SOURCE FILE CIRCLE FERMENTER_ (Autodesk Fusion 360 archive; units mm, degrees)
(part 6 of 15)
sketch "Schizzo15" plane through (40, 0, 0) normal (-1, 0, 0) x axis (0, -1, 0)
  line L1 (88.4, -53.5) -> (90, -53.5)
  line L2 (88.4, -63.5) -> (88.4, -53.5)
  line L3 (85.4, -63.5) -> (88.4, -63.5)
  curve K1 (78.4501, -76.9501) -> (85.4, -63.5)
  curve K2 (65, -83.9) -> (78.4501, -76.9501)
  line L4 (65, -86.9) -> (65, -83.9)
  line L5 (55, -86.9) -> (65, -86.9)
  line L6 (55, -88.5) -> (55, -86.9)
  line L7 (65, -88.5) -> (55, -88.5)
  curve K3 (90, -63.5) -> (65, -88.5)
  line L8 (90, -53.5) -> (90, -63.5)
  line L9 (94.1435, -92.6435) -> (78.4501, -76.9501)
  line L10 (61.8584, -76.9501) -> (78.4501, -76.9501)
  line L11 (86.9521, -65.1) -> (88.4, -65.1)
  curve K4 (79.1128, -78.5501) -> (86.9521, -65.1)
  line L12 (61.8584, -78.5501) -> (79.1128, -78.5501)
  curve K5 (88.4, -63.5) -> (65, -86.9)
  curve K6 (66.6, -85.4521) -> (79.5815, -78.0815)
  line L13 (66.6, -86.9) -> (66.6, -85.4521)
  point P6 (78.4501, -76.9501)
  point P13 (78.4501, -76.9501)
  coincident P6 P13
  horizontal L10
  dimension "d265_1" angle L9 L10 = 135
  dimension "d266_1" = -1.6
  dimension "d267_1" = -1.6
  dimension "d268_1" = -1.6
extrude "Estrusione18" cut sketch "Schizzo15" profile of L11 K4 K5 K6 L13 against normal blind 70 named "d269_1"
sketch "Schizzo16" plane through (0, -15, 0) normal (0, 1, 0) x axis (-1, 0, 0)
  line L1 (-125, -86.9) -> (-125, -88.5)
  line L2 (-135, -86.9) -> (-125, -86.9)
  line L3 (-135, -83.9) -> (-135, -86.9)
  curve K1 (-135, -83.9) -> (-142.5, -79.9)
  curve K2 (-142.5, -79.9) -> (-160, -86.9)
  line L4 (-160, -88.5) -> (-160, -86.9)
  line L5 (-125, -88.5) -> (-160, -88.5)
  curve K3 (-135, -85.5) -> (-142.5, -81.5)
  curve K4 (-142.5, -81.5) -> (-152.9954, -86.9)
  line L6 (-125, -86.9) -> (-152.9954, -86.9)
  line L7 (-136.6, -83.9) -> (-136.6, -86.9)
  line L8 (-138.6, -84.5053) -> (-138.6, -86.9)
  point P15 (-138.6, -86.9)
  point P16 (-138.6, -84.5053)
  coincident L6 P15
  coincident K3 P16
  perpendicular L6 L8
  dimension "d271_1" = -1.6
  dimension "d272_1" = -1.6
  dimension "d673_1" distance L7 L8 = 2
extrude "Estrusione19" cut sketch "Schizzo16" profile of K3 K4 L6 L8 against normal blind 50 named "d273_1"
sketch "Schizzo17" plane through (0, 0, -13.5) normal (0, 0, 1) x axis (-1, 0, 0)
  line L1 (-125, 90) -> (-125, 88.4)
  line L2 (-160, 90) -> (-125, 90)
  line L3 (-160, 88.4) -> (-160, 90)
  curve K1 (-142.5, 81.4) -> (-160, 88.4)
  curve K2 (-135, 85.4) -> (-142.5, 81.4)
  line L4 (-135, 88.4) -> (-135, 85.4)
  line L5 (-125, 88.4) -> (-135, 88.4)
  line L6 (-136.6, 88.4) -> (-136.6, 86.8515)
  line L7 (-152.9954, 88.4) -> (-136.6, 88.4)
  curve K3 (-142.5, 83) -> (-152.9954, 88.4)
  curve K4 (-136.6, 86.8515) -> (-142.5, 83)
  line L8 (-138.6, 88.4) -> (-138.6, 86.0053)
  point P13 (-138.6, 86.0053)
  point P14 (-138.6, 88.4)
  coincident K4 P13
  coincident L7 P14
  perpendicular L7 L8
  dimension "d275_1" = -1.6
  dimension "d672_1" distance L6 L8 = 2
extrude "Estrusione20" cut sketch "Schizzo17" profile of K3 K4 L7 L8 against normal blind 50 named "d276_1"
sweep "Sweep3" TwistAngle 0 named "d289_1" TaperAngle 0 named "d290_1"
fillet "Raccordo1" radius 0.5 named "d292_1"
extrude "Estrusione21" cut of existing geometry blind -45 (= "-120 mm + 75 mm") named "d293_1"
sketch "Schizzo18" plane through (0, -15, 0) normal (0, 1, 0) x axis (-1, 0, 0)
  line L1 (-150.8209, -86.9) -> (-138.6, -86.9)
  curve K1 (-150.8209, -86.9) -> (-151.0572, -85.9594)
  curve K2 (-142.5, -81.5) -> (-151.0572, -85.9594)
  curve K3 (-138.6, -84.5053) -> (-142.5, -81.5)
  line L2 (-125, -86.9) -> (-125, -88.5)
  line L3 (-135, -86.9) -> (-125, -86.9)
  line L4 (-135, -83.9) -> (-135, -86.9)
  curve K4 (-135, -83.9) -> (-142.5, -79.9)
  curve K5 (-142.5, -79.9) -> (-160, -86.9)
  line L5 (-160, -88.5) -> (-160, -86.9)
  line L6 (-125, -88.5) -> (-160, -88.5)
  line L7 (-138.6, -86.9) -> (-138.6, -84.5053)
  circle C1 centre (-135.4, -85.4) radius 0.85
  point P14 (-135.4, -85.4)
  dimension "DIAM_SEDE_GUARNIZOIONE_1" diameter C1 = 1.7
  dimension "d669_1" distance L4 P14 = 0.4
  dimension "d671_1" distance L3 P14 = 1.5
sweep "Sweep4" sketch "Schizzo18" TwistAngle 0 named "d301_1" TaperAngle 0 named "d302_1"
mirror "Specchio2" mirrorStitchTolerance 0.1 named "d304_1"
sketch "Schizzo19" plane through (0, -15, 0) normal (0, 1, 0) x axis (-1, 0, 0)
  line L1 (-135, -83.9) -> (-135, -84.65)
  curve K1 (-135, -83.9) -> (-142.5, -79.9)
  curve K2 (-142.5, -79.9) -> (-160, -86.9)
  line L2 (-160, -88.5) -> (-160, -86.9)
  line L3 (-125, -88.5) -> (-160, -88.5)
  line L4 (-125, -86.9) -> (-125, -88.5)
  line L5 (-135, -86.9) -> (-125, -86.9)
  line L6 (-150.8209, -86.9) -> (-138.6, -86.9)
  curve K3 (-150.8209, -86.9) -> (-151.0572, -85.9594)
  curve K4 (-142.5, -81.5) -> (-151.0572, -85.9594)
  curve K5 (-138.6, -84.5053) -> (-142.5, -81.5)
  line L7 (-135, -86.15) -> (-135, -86.9)
  line L8 (-138.6, -86.9) -> (-138.6, -84.5053)
  arc A1 centre (-135.4, -85.4) radius 0.85 clockwise from (-135, -86.15) to (-135, -84.65)
  arc A2 centre (-135.4, -85.4) radius 0.85 clockwise from (-135, -86.15) to (-135, -84.65)
  circle C1 centre (-135.4, -85.4) radius 0.875
  concentric A2 C1
  dimension "d305_1" diameter C1 = 1.75
sweep "Sweep5" sketch "Schizzo19" TwistAngle 0 named "d310_1" TaperAngle 0 named "d311_1" bodies "GUARNIZIONE"
mirror "Specchio3" mirrorStitchTolerance 0.1 named "d313_1" bodies "GUARNIZIONE (1)"
work_plane "Piano di lavoro2" AlongDistance -2 named "d328_1"
sketch "Schizzo21" plane through (158, 0, 0) normal (1, 0, 0) x axis (0, 1, 0)
  line L1 (-81.4, -63.5) -> (-81.4, -13.5)
  curve K1 (-81.4, -63.5) -> (-65, -79.9)
  line L2 (-65, -79.9) -> (-15, -79.9)
  line L3 (-65, -81.4) -> (-15, -81.4)
  curve K2 (-82.9, -63.5) -> (-65, -81.4)
  line L4 (-82.9, -63.5) -> (-82.9, -13.5)
  line L5 (-15, -13.5) -> (-15, -81.4)
  line L6 (-82.9, -13.5) -> (-15, -13.5)
  horizontal L6
  vertical L5
  dimension "d329_1" = -1.5
extrude "Estrusione23" new body sketch "Schizzo21" profile of L3 K2 L4 L5 L6 against normal blind 3 named "d330_1" bodies "TEST ACRILICO DAVANTI"
sketch "Schizzo22" plane through (0, 0, -13.5) normal (0, 0, 1) x axis (-1, 0, 0)
  line L1 (-125, 88.4) -> (-135, 88.4)
  line L2 (-125, 90) -> (-125, 88.4)
  line L3 (-160, 90) -> (-125, 90)
  line L4 (-160, 88.4) -> (-160, 90)
  curve K1 (-142.5, 81.4) -> (-160, 88.4)
  curve K2 (-135, 85.4) -> (-142.5, 81.4)
  line L5 (-135, 88.4) -> (-135, 87.65)
  curve K3 (-142.5, 83) -> (-138.6, 86.0053)
  curve K4 (-151.0572, 87.4594) -> (-142.5, 83)
  curve K5 (-151.0572, 87.4594) -> (-150.8209, 88.4)
  line L6 (-138.6, 88.4) -> (-150.8209, 88.4)
  curve K6 (-142.5, 80.9) -> (-160, 87.9)
  line L7 (-160, 90) -> (-160, 87.9)
  line L8 (-158, 15) -> (-158, 82.9)
  line L9 (-155, 15) -> (-158, 15)
  line L10 (-155, 82.9) -> (-155, 15)
  line L11 (-158, 82.9) -> (-155, 82.9)
  line L12 (-158, 82.9) -> (-158, 77.9)
  line L13 (-155, 82.9) -> (-158, 82.9)
  line L14 (-155, 86.9365) -> (-155, 82.9)
  curve K7 (-164, 77.9) -> (-158, 77.9)
  curve K8 (-168, 77.9) -> (-164, 77.9)
  curve K9 (-170, 88.4) -> (-168, 77.9)
  curve K10 (-174, 88.4) -> (-170, 88.4)
  curve K11 (-180, 88.4) -> (-174, 88.4)
  curve K12 (-180, 88.4) -> (-158, 77.9)
  line L15 (-160, 90) -> (-160, 87.9)
  line L16 (-180, 90) -> (-160, 90)
  line L17 (-180, 88.4) -> (-180, 90)
  line L18 (-151.4, 82.9) -> (-155, 82.9)
  line L19 (-151.4, 85.247) -> (-151.4, 82.9)
  line L20 (-138.6, 86.0053) -> (-138.6, 88.4)
  line L21 (-135, 86.15) -> (-135, 85.4)
  arc A1 centre (-135.4, 86.9) radius 0.85 clockwise from (-135, 86.15) to (-135, 87.65)
  point P7 (-160, 90)
  point P18 (-160, 90)
  point P23 (-158, 77.9)
  point P19 (-158, 82.9)
  point P24 (-158, 82.9)
  point P22 (-155, 82.9)
  point P25 (-155, 82.9)
  point P26 (-155, 82.9)
  point P27 (-155, 86.9365)
  point P33 (-160, 90)
  point P36 (-151.4, 85.247)
  point P28 (-164, 77.9)
  point P29 (-168, 77.9)
  point P31 (-174, 88.4)
  point P32 (-180, 88.4)
  point P30 (-170, 88.4)
  point P34 (-180, 90)
  point P35 (-151.4, 82.9)
  coincident P7 P18
  perpendicular L3 L7
  coincident L8 P23
  coincident P19 P24
  perpendicular L11 L12
  coincident P22 P25
  coincident P22 P26
  coincident K6 P27
  perpendicular L11 L14
  horizontal K10
  horizontal K7
  perpendicular L15 L16
  parallel L15 L17
  horizontal K8
  horizontal K11
  coincident P18 P33
  perpendicular L14 L18
  coincident K6 P36
  perpendicular L18 L19
  dimension "d332_1" = 0.5
  dimension "d335_1" distance P23 P24 = 5
  dimension "d336_1" distance L3 L13 = 7.1
  dimension "d337_1" distance P23 P28 = 6
  dimension "d338_1" distance P23 P29 = 10
  dimension "d339_1" distance P31 P32 = 6
  dimension "d340_1" distance P30 P32 = 10
  dimension "d342_1" distance P32 P34 = 1.6
  dimension "d343_1" distance P33 P34 = 20
  dimension "d373_1" distance P25 P35 = 3.6
extrude "Estrusione24" new body sketch "Schizzo22" profile of L4 K6 L7 L8 L11 L12 L13 L14 K12 L15 L16 L17 against normal blind 50 named "d344_1"
sweep "Sweep6" TwistAngle 0 named "d350_1" TaperAngle 0 named "d351_1" bodies "PROFILO BASE PORTA"
remove_body "RimuoviCorpo1"
chamfer "Smusso2" distance 0.8 named "d352_1"
component_from_bodies "Corpo->Comp1"
component_from_bodies "Corpo->Comp2"
extrude "Estrusione1" add of existing geometry blind 27.5 (= "( 205 / 2 ) * 1 mm - 75 mm") named "d353_1"
extrude "Estrusione2" add of existing geometry blind 15 (= "90 mm - 75 mm") named "d355_1"
extrude "Estrusione3" add of existing geometry blind 85 (= "( 320 / 2 ) * 1 mm - 75 mm") named "d357_1"
extrude "Estrusione1" add of existing geometry blind 15 named "d359_1"
extrude "Estrusione2" add of existing geometry blind 27.5 named "d361_1"
sketch "Schizzo3" plane through (0, 0, 0) normal (0, 1, 0) x axis (-1, 0, 0)
  line L1 (-160, -87.7) -> (-160.8, -88.5)
  line L2 (-160, -86.4) -> (-160, -87.7)
  curve K1 (-151.4, -83.747) -> (-160, -86.4)
  line L3 (-151.4, -81.4) -> (-151.4, -83.747)
  line L4 (-158, -81.4) -> (-151.4, -81.4)
  line L5 (-158, -76.4) -> (-158, -81.4)
  curve K2 (-180, -86.9) -> (-158, -76.4)
  line L6 (-180, -88.5) -> (-180, -86.9)
  line L7 (-160.8, -88.5) -> (-180, -88.5)
  line L8 (-158, -86.2311) -> (-158, -81.4)
  point P7 (-158, -81.4)
  point P11 (-158, -81.4)
  point P12 (-158, -86.2311)
  coincident P7 P11
  coincident K1 P12
  perpendicular L4 L8
extrude "Estrusione5" cut sketch "Schizzo3" profile of K1 L3 L4 L8 against normal blind 65 named "d384_1"
sketch "Schizzo4" plane through (0, 0, 14) normal (0, 0, 1) x axis (-1, 0, 0)
  line L1 (-160.8, 90) -> (-160, 89.2)
  line L2 (-180, 90) -> (-160.8, 90)
  line L3 (-180, 88.4) -> (-180, 90)
  curve K1 (-158, 77.9) -> (-180, 88.4)
  line L4 (-158, 82.9) -> (-158, 77.9)
  line L5 (-151.4, 82.9) -> (-158, 82.9)
  line L6 (-151.4, 85.247) -> (-151.4, 82.9)
  curve K2 (-160, 87.9) -> (-151.4, 85.247)
  line L7 (-160, 89.2) -> (-160, 87.9)
  line L8 (-158, 87.7311) -> (-158, 82.9)
  point P7 (-158, 82.9)
  point P11 (-158, 82.9)
  point P12 (-158, 87.7311)
  coincident P7 P11
  coincident K2 P12
  perpendicular L5 L8
extrude "Estrusione6" cut sketch "Schizzo4" profile of L5 L6 K2 L8 against normal blind 77.5 named "d386_1"
sketch "Schizzo6" plane through (158, 0, 0) normal (-1, 0, 0) x axis (0, -1, 0)
  curve K1 (65, -76.4) -> (77.9, -63.5)
  line L1 (0, -76.4) -> (65, -76.4)
  line L2 (0, -86.2311) -> (0, -76.4)
  line L3 (0, -86.2311) -> (65, -86.2311)
  line L4 (65, -81.4) -> (65, -86.2311)
  curve K2 (65, -81.4) -> (82.9, -63.5)
  line L5 (87.7311, -63.5) -> (82.9, -63.5)
  line L6 (87.7311, -63.5) -> (87.7311, 14)
  line L7 (77.9, 14) -> (87.7311, 14)
  line L8 (77.9, -63.5) -> (77.9, 14)
  line L9 (86.9, -62.4362) -> (86.9, -63.5)
  line L10 (86.9, 14) -> (86.9, -62.4362)
  line L11 (0, -85.4) -> (65, -85.4)
  line L12 (0, 14) -> (0, -85.4)
  line L13 (86.9, 14) -> (0, 14)
  point P12 (86.9, -63.5)
  point P14 (86.9, 14)
  point P15 (65, -85.4)
  point P16 (0, -85.4)
  coincident L5 P12
  perpendicular L5 L9
  coincident L7 P14
  perpendicular L7 L10
  coincident L4 P15
  coincident L2 P16
  perpendicular L2 L11
  horizontal L13
  vertical L12
  dimension "d398_1" distance L10 L12 = 86.9
  dimension "d399_1" distance L11 L13 = 99.4
extrude "Estrusione7" new body sketch "Schizzo6" profile of K1 L1 L2 L4 K2 L5 L7 L8 L9 L10 L11 L12 L13 along normal blind 3 named "d396_1" bodies "ACRILICO SPORTELLO"
sketch "Schizzo7" plane through (0, 0, 14) normal (0, 0, 1) x axis (-1, 0, 0)
  line L1 (-158, 87.7311) -> (-158, 77.9)
  curve K1 (-160, 87.9) -> (-158, 87.7311)
  line L2 (-160, 89.2) -> (-160, 87.9)
  line L3 (-160.8, 90) -> (-160, 89.2)
  line L4 (-180, 90) -> (-160.8, 90)
  line L5 (-180, 88.4) -> (-180, 90)
  curve K2 (-158, 77.9) -> (-180, 88.4)
  line L6 (-151.4, 85.247) -> (-151.4, 82.9)
  curve K3 (-151.4, 85.247) -> (-158, 87.7311)
  line L7 (-158, 82.9) -> (-158, 87.7311)
  line L8 (-151.4, 82.9) -> (-158, 82.9)
  line L9 (-158, 0) -> (-158, 86.9)
  line L10 (-155, 0) -> (-158, 0)
  line L11 (-155, 86.9) -> (-155, 0)
  line L12 (-158, 86.9) -> (-155, 86.9)
  line L13 (-155, 88.0285) -> (-155, 86.9)
  point P16 (-155, 86.9)
  point P17 (-155, 86.9)
  coincident P16 P17
  perpendicular L12 L13
extrude "Estrusione8" new body sketch "Schizzo7" profile of L6 K3 L8 L11 L13 against normal blind 77.5 named "d400_1"
sketch "Schizzo8" plane through (0, 0, 0) normal (0, 1, 0) x axis (-1, 0, 0)
  line L1 (-158, -76.4) -> (-158, -86.2311)
  curve K1 (-180, -86.9) -> (-158, -76.4)
  line L2 (-180, -88.5) -> (-180, -86.9)
  line L3 (-160.8, -88.5) -> (-180, -88.5)
  line L4 (-160, -87.7) -> (-160.8, -88.5)
  line L5 (-160, -86.4) -> (-160, -87.7)
  curve K2 (-158, -86.2311) -> (-160, -86.4)
  line L6 (-158, -85.4) -> (-158, 14)
  line L7 (-155, -85.4) -> (-158, -85.4)
  line L8 (-155, 14) -> (-155, -85.4)
  line L9 (-158, 14) -> (-155, 14)
  line L10 (-158, -86.2311) -> (-158, -81.4)
  curve K3 (-151.4, -83.747) -> (-158, -86.2311)
  line L11 (-151.4, -81.4) -> (-151.4, -83.747)
  line L12 (-158, -81.4) -> (-151.4, -81.4)
  line L13 (-155, -87.0144) -> (-155, -85.4)
  point P11 (-155, -85.4)
  point P17 (-155, -85.4)
  coincident P11 P17
  perpendicular L7 L13
extrude "Estrusione9" new body sketch "Schizzo8" profile of L8 K3 L11 L12 L13 against normal blind 65 named "d402_1"
sketch "Schizzo9" plane through (155, 0, 0) normal (-1, 0, 0) x axis (0, -1, 0)
  line L1 (65, -81.4) -> (65, -85.4)
  curve K1 (82.9, -63.5) -> (65, -81.4)
  line L2 (86.9, -63.5) -> (82.9, -63.5)
  line L3 (86.9, 14) -> (86.9, -63.5)
  line L4 (0, 14) -> (86.9, 14)
  line L5 (0, -85.4) -> (0, 14)
  line L6 (65, -85.4) -> (0, -85.4)
  curve K2 (65, -76.4) -> (77.9, -63.5)
  line L7 (77.9, 14) -> (77.9, -63.5)
  line L8 (0, -76.4) -> (65, -76.4)
  line L9 (65, -81.4) -> (0, -81.4)
  line L10 (82.9, 14) -> (85.247, 14)
  line L11 (82.9, -63.5) -> (82.9, 14)
  line L12 (85.247, -63.5) -> (82.9, -63.5)
  line L13 (85.247, 14) -> (85.247, -63.5)
extrude "Estrusione10" add sketch "Schizzo9" profile of K1 L4 L5 K2 L7 L8 L9 L11 along normal blind 3.6 named "d404_1"
sketch "Schizzo10" plane through (151.4, 0, 0) normal (-1, 0, 0) x axis (0, -1, 0)
  line L1 (77.9, 14) -> (85.247, 14)
  line L2 (77.9, -63.5) -> (77.9, 14)
  curve K1 (65, -76.4) -> (77.9, -63.5)
  line L3 (0, -76.4) -> (65, -76.4)
  line L4 (0, -83.747) -> (0, -76.4)
  line L5 (65, -83.747) -> (0, -83.747)
  line L6 (65, -81.4) -> (65, -83.747)
  curve K2 (82.9, -63.5) -> (65, -81.4)
  line L7 (85.247, -63.5) -> (82.9, -63.5)
  line L8 (85.247, 14) -> (85.247, -63.5)
  line L9 (65, -63.5) -> (65, -81.4)
  line L10 (82.9, -63.5) -> (65, -63.5)
  line L11 (91.705, -90.205) -> (65, -63.5)
  line L12 (65, -80.0735) -> (0, -80.0735)
  line L13 (81.5735, -63.5) -> (81.5735, 14)
  point P9 (65, -81.4)
  point P12 (65, -81.4)
  point P10 (82.9, -63.5)
  point P14 (82.9, -63.5)
  point P16 (0, -80.0735)
  point P17 (65, -80.0735)
  point P18 (0, -80.0735)
  point P19 (45, -80.0735)
  point P20 (81.5735, 14)
  point P21 (81.5735, -63.5)
  point P22 (81.5735, -43.5)
  point P23 (81.5735, 14)
  coincident P9 P12
  parallel L6 L9
  coincident P10 P14
  horizontal L10
  midpoint L4 P16
  coincident L9 P17
  perpendicular L9 L12
  coincident L12 P18
  coincident L12 P19
  midpoint L1 P20
  coincident L10 P21
  perpendicular L10 L13
  coincident L13 P22
  coincident L13 P23
  coincident P16 P18
  coincident P20 P23
  dimension "d406_1" angle L10 L11 = 45
  dimension "d408_1" distance P18 P19 = 45
  dimension "d409_1" distance L6 P19 = 20
  dimension "d410_1" distance P21 P22 = 20
  dimension "d413_1" distance P20 P22 = 57.5
  dimension "d648_1" distance P22 P23 = 57.5
hole "Foratura1" HoleDepth 12 named "d414_1" HoleDiameter 3.5 named "d415_1" TipAngle 180 named "d416_1" CBDepth 3 named "d417_1" CBDiameter 6 named "d418_1"
fillet "Raccordo2" radius 0.5 named "d436_1"
mirror "Specchio3" mirrorStitchTolerance 0.1 named "d438_1"
mirror "Specchio4" mirrorStitchTolerance 0.1 named "d440_1"
step "Vite5"
joint "Assembla5" alignAngle 0 named "d441_1" alignOffsetX 0 named "d442_1" alignOffsetY 0 named "d443_1" alignOffsetZ 0 named "d444_1"
step "Vite6"
joint "Assembla6" alignAngle 0 named "d445_1" alignOffsetX 0 named "d446_1" alignOffsetY 0 named "d447_1" alignOffsetZ 0 named "d448_1"
step "Vite7"
joint "Assembla7" alignAngle 0 named "d449_1" alignOffsetX 0 named "d450_1" alignOffsetY 0 named "d451_1" alignOffsetZ 0 named "d452_1"
step "Vite8"
joint "Assembla8" alignAngle 0 named "d453_1" alignOffsetX 0 named "d454_1" alignOffsetY 0 named "d455_1" alignOffsetZ 0 named "d456_1"
step "Vite9"
joint "Assembla9" alignAngle 0 named "d457_1" alignOffsetX 0 named "d458_1" alignOffsetY 0 named "d459_1" alignOffsetZ 0 named "d460_1"
step "Vite10"
joint "Assembla10" alignAngle 0 named "d461_1" alignOffsetX 0 named "d462_1" alignOffsetY 0 named "d463_1" alignOffsetZ 0 named "d464_1"
step "Vite11"
joint "Assembla11" alignAngle 0 named "d465_1" alignOffsetX 0 named "d466_1" alignOffsetY 0 named "d467_1" alignOffsetZ 0 named "d468_1"
step "Vite12"
joint "Assembla12" alignAngle 0 named "d469_1" alignOffsetX 0 named "d470_1" alignOffsetY 0 named "d471_1" alignOffsetZ 0 named "d472_1"
step "Vite13"
joint "Assembla13" alignAngle 0 named "d473_1" alignOffsetX 0 named "d474_1" alignOffsetY 0 named "d475_1" alignOffsetZ 0 named "d476_1"
step "Vite14"
joint "Assembla14" alignAngle 0 named "d477_1" alignOffsetX 0 named "d478_1" alignOffsetY 0 named "d479_1" alignOffsetZ 0 named "d480_1"
step "Vite15"
joint "Assembla15" alignAngle 0 named "d481_1" alignOffsetX 0 named "d482_1" alignOffsetY 0 named "d483_1" alignOffsetZ 0 named "d484_1"
step "Vite16"
joint "Assembla16" alignAngle 0 named "d485_1" alignOffsetX 0 named "d486_1" alignOffsetY 0 named "d487_1" alignOffsetZ 0 named "d488_1"
step "Vite17"
joint "Assembla17" alignAngle 0 named "d489_1" alignOffsetX 0 named "d490_1" alignOffsetY 0 named "d491_1" alignOffsetZ 0 named "d492_1"
step "Vite18"
joint "Assembla18" alignAngle 0 named "d493_1" alignOffsetX 0 named "d494_1" alignOffsetY 0 named "d495_1" alignOffsetZ 0 named "d496_1"
step "Vite19"
joint "Assembla19" alignAngle 0 named "d497_1" alignOffsetX 0 named "d498_1" alignOffsetY 0 named "d499_1" alignOffsetZ 0 named "d500_1"
step "Vite20"
joint "Assembla20" alignAngle 0 named "d501_1" alignOffsetX 0 named "d502_1" alignOffsetY 0 named "d503_1" alignOffsetZ 0 named "d504_1"
component_from_bodies "Corpo->Comp1"
mirror "Specchio5" mirrorStitchTolerance 0.1 named "d506_1"
mirror "Specchio6" mirrorStitchTolerance 0.1 named "d508_1"
component_from_bodies "Corpo->Comp2"
thread "Filettatura1"
mirror "Specchio1" mirrorStitchTolerance 0.1 named "d364_1"
mirror "Specchio2" mirrorStitchTolerance 0.1 named "d366_1"
component_from_bodies "Corpo->Comp3"
joint "Assembla21" alignAngle 0 named "d509_1" alignOffsetX 0 named "d510_1" alignOffsetY 0 named "d511_1" alignOffsetZ 0 named "d512_1"
joint "Assembla22" alignAngle 0 named "d513_1" alignOffsetX 0 named "d514_1" alignOffsetY 0 named "d515_1" alignOffsetZ 0 named "d516_1"
chamfer "Smusso1" distance 1 named "d674_1"
sketch "Schizzo1" plane through (0, 0, 0) normal (-1, 0, 0) x axis (0, -1, 0)
  curve K1 (66.6, -86.8951) -> (88.3975, -65.1)
  line L1 (66.6, -85.4521) -> (66.6, -86.8951)
  curve K2 (79.5815, -78.0815) -> (66.6, -85.4521)
  curve K3 (86.9521, -65.1) -> (79.5815, -78.0815)
  line L2 (88.3975, -65.1) -> (86.9521, -65.1)
  line L3 (85.4, -63.5) -> (86.15, -63.5)
  curve K4 (78.4501, -76.9501) -> (85.4, -63.5)
  curve K5 (65, -83.9) -> (78.4501, -76.9501)
  line L4 (65, -84.65) -> (65, -83.9)
  line L5 (55, -86.9) -> (65, -86.9)
  line L6 (55, -88.5) -> (55, -86.9)
  line L7 (65, -88.5) -> (55, -88.5)
  curve K6 (90, -63.5) -> (65, -88.5)
  line L8 (90, -53.5) -> (90, -63.5)
  line L9 (88.4, -53.5) -> (90, -53.5)
  line L10 (88.4, -63.5) -> (88.4, -53.5)
  line L11 (65, -86.9) -> (65, -86.15)
  line L12 (87.65, -63.5) -> (88.4, -63.5)
  arc A1 centre (86.9, -63.9) radius 0.85 clockwise from (87.65, -63.5) to (86.15, -63.5)
  arc A2 centre (65.4, -85.4) radius 0.85 clockwise from (65, -84.65) to (65, -86.15)
extrude "Estrusione1" new body sketch "Schizzo1" profile of K1 L1 K2 K3 L2 against normal blind 30 named "d517_1"
fillet "Raccordo1" radius 1 named "d520_1"
work_plane "Piano di lavoro1"
remove_instance "RimuoviIstanza1"
remove_body "RimuoviCorpo4"
component_from_bodies "Corpo->Comp3"
component_from_bodies "Corpo->Comp4"
extrude "Estrusione1" add of existing geometry blind 85 named "d521_1"
extrude "Estrusione2" add of existing geometry blind 27.5 named "d523_1"
extrude "Estrusione1" add of existing geometry blind 85 named "d525_1"
extrude "Estrusione2" add of existing geometry blind 15 named "d527_1"
remove_body "RimuoviCorpo7"
remove_body "RimuoviCorpo8"
sketch "Schizzo2" plane through (0, -79.2125, -79.2737) normal (0, -0.7068, -0.7074) x axis (1, 0, 0)
  line L1 (0, 11.5655) -> (30, 11.5655)
  line L2 (30, 11.5655) -> (30, 1.1037)
  line L3 (0, 1.1037) -> (30, 1.1037)
  line L4 (0, 11.5655) -> (0, 1.1037)
  line L5 (30, -9.3661) -> (0, -9.3661)
  line L6 (0, 1.1037) -> (0, -9.3661)
  line L7 (30, 1.1037) -> (0, 1.1037)
  line L8 (30, 1.1037) -> (30, -9.3661)
  circle C1 centre (15, 1.1037) radius 2
  point P10 (15, 1.1037)
  coincident L7 P10
  dimension "d529_1" diameter C1 = 4
  dimension "d544_1" distance L8 P10 = 15
extrude "Estrusione2" cut sketch "Schizzo2" profile of L3 L7 C1 distance -14.039 named "d531_1"
work_axis "AsseLavoro1"
work_plane "Piano di lavoro2" RotateAngle 0 named "d533_1"
sketch "Schizzo3" plane through (15, 0, 0) normal (1, 0, 0) x axis (0, 1, 0)
  curve K1 (-71.4268, -84.7327) -> (-71.7899, -86.6906)
  curve K2 (-71.7899, -86.6906) -> (-88.1875, -70.3056)
  curve K3 (-88.1875, -70.3056) -> (-86.2311, -69.9353)
  curve K4 (-86.2311, -69.9353) -> (-79.5815, -78.0815)
  curve K5 (-79.5815, -78.0815) -> (-71.4268, -84.7327)
  curve K6 (-71.7899, -86.6906) -> (-71.4268, -84.7327)
  curve K7 (-79.5815, -78.0815) -> (-71.4268, -84.7327)
  curve K8 (-86.2311, -69.9353) -> (-79.5815, -78.0815)
  curve K9 (-86.2311, -69.9353) -> (-88.1875, -70.3056)
  curve K10 (-71.7899, -86.6906) -> (-88.1875, -70.3056)
  line L1 (-85.3935, -83.898) -> (-72.103, -70.5972)
  line L2 (-82.9743, -81.4769) -> (-83.3984, -81.9013)
  line L3 (-77.3152, -87.1316) -> (-82.9743, -81.4769)
  line L4 (-77.7393, -87.556) -> (-83.3984, -81.9013)
  line L5 (-77.3152, -87.1316) -> (-77.7393, -87.556)
  line L6 (-88.6333, -75.8222) -> (-82.9743, -81.4769)
  line L7 (-82.9743, -81.4769) -> (-83.3984, -81.9013)
  line L8 (-88.6333, -75.8222) -> (-89.0574, -76.2466)
  line L9 (-89.0574, -76.2466) -> (-83.3984, -81.9013)
  line L10 (-94.0535, -81.2466) -> (-89.0574, -76.2466)
  line L11 (-82.7355, -92.556) -> (-94.0535, -81.2466)
  line L12 (-77.7393, -87.556) -> (-82.7355, -92.556)
  point P14 (-83.3984, -81.9013)
  point P20 (-83.3984, -81.9013)
  point P15 (-82.9743, -81.4769)
  point P18 (-82.9743, -81.4769)
  point P16 (-77.3152, -87.1316)
  point P19 (-88.6333, -75.8222)
  point P17 (-77.7393, -87.556)
  point P21 (-89.0574, -76.2466)
  point P23 (-82.7355, -92.556)
  coincident K10 P14
  coincident L1 P14
  parallel L1 L2
  perpendicular L1 L3
  perpendicular L1 L4
  perpendicular L4 L5
  symmetric L1 P14 P20
  symmetric L1 P15 P18
  symmetric L1 P16 P19
  symmetric L1 P17 P21
  perpendicular L9 L10
  perpendicular L10 L11
  perpendicular L11 L12
  dimension "d534_1" distance P14 P15 = 0.6
  dimension "d535_1" distance P14 P17 = 8
  dimension "d539_1" distance P17 P23 = 5
extrude "Estrusione3" cut sketch "Schizzo3" profile of K2 K10 L1 L2 L3 L4 L5 L6 L7 L8 L9 L10 L11 L12 distance 18.695 named "d536_1"
work_plane "Piano di lavoro3" RotateAngle 135 named "d540_1"
sketch "Schizzo4" plane through (0, -78.8315, -78.8315) normal (0, -0.7071, -0.7071) x axis (1, 0, 0)
  curve K1 (13, 1.0607) -> (17, 1.0607)
  curve K2 (17, 1.0607) -> (13, 1.0607)
  line L1 (15, 1.0575) -> (15, 1.0647)
  circle C1 centre (15, 1.0647) radius 5
  point P4 (15, 1.0647)
  point P6 (15, 1.0647)
  coincident P4 P6
  dimension "d541_1" diameter C1 = 10
extrude "Estrusione4" cut sketch "Schizzo4" profile of K1 K2 C1 along normal blind 0.8 named "d542_1"
fillet "Raccordo2" radius 1 named "d546_1" 1 named "d548_1"
mirror "Specchio1" mirrorStitchTolerance 0.1 named "d550_1"
component_from_bodies "Corpo->Comp1"
component_insert "Inserimento componente1"
component_insert "Inserimento componente2"
joint "Assembla1" alignAngle 0 named "d551_1" alignOffsetX 0 named "d552_1" alignOffsetY 0 named "d553_1" alignOffsetZ 0 named "d554_1"
joint "Assembla2" alignAngle 0 named "d555_1" alignOffsetX 0 named "d556_1" alignOffsetY 0 named "d557_1" alignOffsetZ 0 named "d558_1"
work_plane "Piano di lavoro1" RotateAngle 45 named "d559_1"
sketch "Schizzo1" plane through (0, -77.7001, -77.7001) normal (0, 0.7071, 0.7071) x axis (-1, 0, 0)
  line L1 (0, 1.0607) -> (0, 15.4856)
  line L2 (0, 1.0607) -> (-85, 1.0607)
  line L3 (-16, 1.0607) -> (0, 1.0607)
  point P3 (0, 1.0607)
  point P5 (0, 1.0607)
  point P6 (-16, 1.0607)
  point P7 (-16, 1.0607)
  point P8 (-14, 1.0607)
  coincident P3 P5
  perpendicular L1 L3
  coincident P6 P7
  coincident L2 P8
  dimension "d560_1" distance P5 P6 = 16
  dimension "d561_1" distance P7 P8 = 2
hole "Foratura1" HoleDepth 6 named "d562_1" HoleDiameter 3.5 named "d563_1" TipAngle 180 named "d564_1" CSDiameter 6.7 named "d565_1" CSAngle 90 named "d566_1"
sketch "Schizzo2" plane through (0, -77.7001, -77.7001) normal (0, 0.7071, 0.7071) x axis (-1, 0, 0)
  curve K1 (-10.65, 1.0607) -> (-15, 4.0417)
  line L1 (-15, 4.0417) -> (-15, 2.4968)
  curve K2 (-15, -1.9204) -> (-10.65, 1.0607)
  curve K3 (-15, 4.0417) -> (-19.35, 1.0607)
  curve K4 (-19.35, 1.0607) -> (-15, -1.9204)
  line L2 (-15, -0.3755) -> (-15, -1.9204)
  line L3 (-16.8101, -0.4905) -> (-13.1899, 2.6119)
  line L4 (-17, -0.6893) -> (-13, -0.6893)
  line L5 (-15, -0.3755) -> (-15, -1.9204)
  line L6 (-15, 4.0417) -> (-15, 2.4968)
  arc A1 centre (-14, 1.0607) radius 1.75 clockwise from (-15, 2.4968) to (-12.25, 1.0607)
  arc A2 centre (-16, 1.0607) radius 1.75 clockwise from (-15, -0.3755) to (-17.75, 1.0607)
  arc A3 centre (-14, 1.0607) radius 1.75 clockwise from (-12.25, 1.0607) to (-15, -0.3755)
  arc A4 centre (-16, 1.0607) radius 1.75 clockwise from (-17.75, 1.0607) to (-15, 2.4968)
  point P14 (-13.1899, 2.6119)
  point P15 (-16.8101, -0.4905)
  midpoint A1 P14
  midpoint A2 P15
work_plane "Piano di lavoro2" AlongDistance -15 named "d569_1"
sketch "Schizzo4" plane through (15, 0, 0) normal (-1, 0, 0) x axis (0, -1, 0)
  line L1 (79.5815, -78.0815) -> (78.344, -79.3189)
  curve K1 (80.7035, -74.9877) -> (78.4501, -76.9501)
  curve K2 (78.4501, -76.9501) -> (76.4877, -79.2035)
  line L2 (80.8189, -74.8943) -> (80.8189, -76.844)
  line L3 (76.3943, -79.3189) -> (78.344, -79.3189)
  curve K3 (78.566, -79.097) -> (76.4877, -79.2035)
  line L4 (80.8189, -76.844) -> (79.5815, -78.0815)
  curve K4 (80.7035, -74.9877) -> (80.597, -77.066)
  point P8 (80.8189, -74.8943)
  point P2 (78.344, -79.3189)
  point P9 (78.344, -79.3189)
  point P10 (76.3943, -79.3189)
  coincident K1 P8
  vertical L2
  coincident P2 P9
  coincident K2 P10
  perpendicular L2 L3
extrude "Estrusione5" cut sketch "Schizzo4" distance 1 named "d570_1"
sketch "Schizzo1" plane through (-30, 0, 0) normal (-1, 0, 0) x axis (0, -1, 0)
  line L1 (85.8919, -78.5615) -> (80.0566, -84.3923)
  curve K1 (85.8919, -78.5615) -> (88.1875, -70.3056)
  curve K2 (86.2311, -69.9353) -> (88.1875, -70.3056)
  curve K3 (86.2311, -69.9353) -> (79.5815, -78.0815)
  curve K4 (79.5815, -78.0815) -> (71.4268, -84.7327)
  curve K5 (71.7899, -86.6906) -> (71.4268, -84.7327)
  curve K6 (71.7899, -86.6906) -> (80.0566, -84.3923)
  line L2 (85.7303, -78.4402) -> (79.9356, -84.2305)
  curve K7 (85.7303, -78.4402) -> (87.9884, -70.2871)
  curve K8 (86.4232, -69.9908) -> (87.9884, -70.2871)
  curve K9 (86.4232, -69.9908) -> (79.7229, -78.2229)
  curve K10 (79.7229, -78.2229) -> (71.4814, -84.9251)
  curve K11 (71.7719, -86.4914) -> (71.4814, -84.9251)
  curve K12 (71.7719, -86.4914) -> (79.9356, -84.2305)
  line L3 (88.088, -69.2165) -> (87.9884, -70.2871)
  line L4 (70.2461, -86.629) -> (71.7719, -86.4914)
  dimension "d572_1" = 0.2
extrude "Estrusione1" cut sketch "Schizzo1" profile of L1 K1 K2 K5 K6 L2 K7 K12 L3 L4 against normal blind 60 named "d573_1"
sketch "Schizzo1" plane through (0, 0, 0) normal (0, 1, 0) x axis (-1, 0, 0)
  line L1 (-135, -83.9) -> (-135, -84.65)
  curve K1 (-142.5, -79.9) -> (-135, -83.9)
  curve K2 (-160, -86.9) -> (-142.5, -79.9)
  line L2 (-160, -88.5) -> (-160, -86.9)
  line L3 (-125, -88.5) -> (-160, -88.5)
  line L4 (-125, -86.9) -> (-125, -88.5)
  line L5 (-135, -86.9) -> (-125, -86.9)
  line L6 (-150.8209, -86.9) -> (-139.6, -86.9)
  curve K3 (-151.0572, -85.9594) -> (-150.8209, -86.9)
  curve K4 (-142.5, -81.5) -> (-151.0572, -85.9594)
  curve K5 (-139.3951, -83.8988) -> (-142.5, -81.5)
  line L7 (-135, -86.15) -> (-135, -86.9)
  line L8 (-138.6, -85.9) -> (-138.6, -85.5053)
  line L9 (-139.6, -86.9) -> (-138.6, -85.9)
  line L10 (-139.3951, -83.8988) -> (-138.6, -85.5053)
  arc A1 centre (-135.4, -85.4) radius 0.85 clockwise from (-135, -86.15) to (-135, -84.65)
extrude "Estrusione1" new body sketch "Schizzo1" profile of L6 K3 K4 K5 against normal blind 15 named "d575_1"
work_plane "Piano di lavoro1" RotateAngle 45 named "d578_1"
sketch "Schizzo3" plane through (111.1565, 0, -111.1565) normal (-0.7071, 0, 0.7071) x axis (0, -1, 0)
  line L1 (0, 39.2418) -> (0, 43.1335)
  line L2 (15, 39.2418) -> (15, 43.1335)
  line L3 (0, 43.1335) -> (15, 43.1335)
  line L4 (0, 41.1335) -> (15, 41.1335)
  line L5 (15, 39.2418) -> (0, 39.2418)
  circle C1 centre (7.5, 41.1335) radius 2
  point P7 (15, 41.1335)
  point P8 (0, 41.1335)
  point P6 (7.5, 41.1335)
  coincident L2 P7
  coincident L1 P8
  perpendicular L1 L4
  coincident P6 L4
  dimension "d579_1" diameter C1 = 4
  dimension "d582_1" distance L3 L4 = 2
  dimension "d583_1" distance L1 P6 = 7.5
work_plane "Piano di lavoro2"
sketch "Schizzo6" plane through (0, 0, -86.9) normal (0, 0, -1) x axis (1, 0, 0)
  line L1 (150.8209, 0) -> (139.6, 0)
  line L2 (150.8209, 15) -> (150.8209, 0)
  line L3 (139.6, 15) -> (150.8209, 15)
  line L4 (143.3209, 15) -> (143.3209, 7.5)
  line L5 (139.6, 0) -> (139.6, 15)
  circle C1 centre (143.3209, 7.5) radius 2
  point P6 (143.3209, 7.5)
  point P7 (143.3209, 7.5)
  coincident P6 P7
  perpendicular L3 L4
  dimension "d588_1" diameter C1 = 4
  dimension "d597_1" distance L2 L4 = 7.5
extrude "Estrusione4" cut sketch "Schizzo6" profile of C1 against normal blind 16.833 named "d589_1"
work_axis "AsseLavoro2"
work_plane "Piano di lavoro3" AlongDistance -4 named "d591_1"
sketch "Schizzo7" plane through (0, 0, -82.9) normal (0, 0, -1) x axis (-1, 0, 0)
  circle C1 centre (-143.3209, -7.5) radius 4
  point P2 (-143.3209, -7.5)
  point P3 (-143.3209, -7.5)
  coincident P2 P3
  dimension "d592_1" diameter C1 = 8
extrude "Estrusione5" cut sketch "Schizzo7" against normal blind 3.353 named "d593_1"
fillet "Raccordo1" radius 0.4 named "d596_1"
component_insert "Inserimento componente1"
mirror "Specchio1" mirrorStitchTolerance 0.1 named "d599_1"
component_from_bodies "Corpo->Comp1"
joint "Assembla1" alignAngle 0 named "d600_1" alignOffsetX 0 named "d601_1" alignOffsetY 0 named "d602_1" alignOffsetZ 0 named "d603_1"
component_insert "Inserimento componente2"
joint "Assembla2" alignAngle 0 named "d604_1" alignOffsetX 0 named "d605_1" alignOffsetY 0 named "d606_1" alignOffsetZ 0 named "d607_1"
sketch "Schizzo6" plane through (0, 0, -88.5) normal (0, 0, -1) x axis (1, 0, 0)
  line L1 (95, 55) -> (0, 55)
  curve K1 (95, 55) -> (125, 25)
  line L2 (125, 0) -> (125, 25)
  line L3 (160, 0) -> (125, 0)
  line L4 (160, 65) -> (160, 0)
  line L5 (85, 65) -> (160, 65)
  line L6 (0, 65) -> (85, 65)
  line L7 (0, 55) -> (0, 65)
  curve K2 (95, 55) -> (125, 25)
  line L8 (125, 0) -> (125, 25)
  line L9 (95, 55) -> (0, 55)
  line L10 (95, 60) -> (0, 60)
  curve K3 (95, 60) -> (130, 25)
  line L11 (130, 0) -> (130, 25)
  point P18 (47.5, 60)
  point P14 (0, 60)
  point P15 (95, 60)
  point P16 (130, 25)
  point P17 (130, 0)
  coincident L10 P18
  dimension "d608_1" = 5
  dimension "d609_1" distance P14 P15 = 95
  dimension "d610_1" distance P16 P17 = 25
  dimension "d611_1" distance P14 P18 = 47.5 (= "( 95 / 2 ) * 1 mm")
extrude "Estrusione6" cut of existing geometry blind -1 named "d623_1"
sketch "Schizzo7" plane through (0, 0, 0) normal (-1, 0, 0) x axis (0, -1, 0)
  curve K1 (66.6, -86.8951) -> (88.3975, -65.1)
  line L1 (66.6, -85.4521) -> (66.6, -86.8951)
  curve K2 (79.5815, -78.0815) -> (66.6, -85.4521)
  curve K3 (86.9521, -65.1) -> (79.5815, -78.0815)
  line L2 (88.3975, -65.1) -> (86.9521, -65.1)
  line L3 (85.4, -63.5) -> (86.15, -63.5)
  curve K4 (78.4501, -76.9501) -> (85.4, -63.5)
  curve K5 (65, -83.9) -> (78.4501, -76.9501)
  line L4 (65, -84.65) -> (65, -83.9)
  line L5 (55, -86.9) -> (65, -86.9)
  line L6 (55, -88.5) -> (55, -86.9)
  line L7 (65, -88.5) -> (55, -88.5)
  curve K6 (90, -63.5) -> (65, -88.5)
  line L8 (90, -53.5) -> (90, -63.5)
  line L9 (88.4, -53.5) -> (90, -53.5)
  line L10 (88.4, -63.5) -> (88.4, -53.5)
  line L11 (86.7843, -67.1) -> (88.3691, -67.1)
  line L12 (68.6, -86.8638) -> (68.6, -85.2845)
  line L13 (65, -86.9) -> (65, -86.15)
  line L14 (87.65, -63.5) -> (88.4, -63.5)
  arc A1 centre (86.9, -63.9) radius 0.85 clockwise from (87.65, -63.5) to (86.15, -63.5)
  arc A2 centre (65.4, -85.4) radius 0.85 clockwise from (65, -84.65) to (65, -86.15)
  point P22 (88.3691, -67.1)
  point P23 (86.7843, -67.1)
  point P24 (68.6, -85.2845)
  point P25 (68.6, -86.8638)
  coincident K1 P22
  coincident K3 P23
  horizontal L11
  coincident K2 P24
  coincident K1 P25
  vertical L12
  dimension "d625_1" distance L2 L11 = 2
  dimension "d626_1" distance L1 L12 = 2
extrude "Estrusione7" add sketch "Schizzo7" profile of K1 L1 K2 K3 L2 L11 L12 against normal blind 110 named "d627_1"
hole "Foratura2" HoleDepth 6 named "d613_1" HoleDiameter 3.5 named "d614_1" TipAngle 180 named "d615_1" CSDiameter 6.7 named "d616_1" CSAngle 90 named "d617_1"
mirror "Specchio1" mirrorStitchTolerance 0.1 named "d619_1"
work_plane "Piano di lavoro3" AlongDistance -8.6 named "d629_1"
work_plane "Piano di lavoro4" AlongDistance -8.6 named "d633_1"
sketch "Schizzo9" plane through (0, -81.4, 0) normal (0, -1, 0) x axis (-1, 0, 0)
  line L1 (-135, -14) -> (-135, 23.5)
  line L2 (-142.5, -14) -> (-160, -14)
  circle C1 centre (-143.321, -6.5) radius 1.75
  point P2 (-143.321, -6.5)
  dimension "d636_1" distance P2 L1 = 8.321
  dimension "d637_1" diameter C1 = 3.5
  dimension "d638_1" distance P2 L2 = 7.5
offset_faces "FacceDiOffset1" distance -0.2 named "d645_1"
offset_faces "FacceDiOffset2" distance -0.1 named "d646_1"
offset_faces "FacceDiOffset3" distance -0.1 named "d647_1"
sketch "Schizzo1" plane through (0, 0, -86.9) normal (0, 0, 1) x axis (-1, 0, 0)
  line L1 (-125, 0) -> (-135, 0)
  line L2 (-125, 25) -> (-125, 0)
  curve K1 (-95, 55) -> (-125, 25)
  line L3 (0, 55) -> (-95, 55)
  line L4 (0, 65) -> (0, 55)
  curve K2 (-95, 55) -> (-125, 25)
  line L5 (0, 55) -> (-95, 55)
  line L6 (-125, 0) -> (-125, 25)
  line L7 (0, 64.5) -> (-95, 64.5)
  curve K3 (-95, 64.5) -> (-134.5, 25)
  line L8 (-134.5, 0) -> (-134.5, 25)
  line L9 (0, 0) -> (0, 55)
  line L10 (-125, 0) -> (0, 0)
  line L11 (-95, 65) -> (0, 65)
  curve K4 (-135, 25) -> (-95, 65)
  line L12 (-135, 0) -> (-135, 25)
  circle C1 centre (-130, 25) radius 1.75
  circle C2 centre (-47.5, 60) radius 1.75
  circle C3 centre (-130, 25) radius 1.75
  circle C4 centre (-95, 60) radius 1.75
  circle C5 centre (-47.5, 60) radius 1.75
  point P8 (0, 55)
  point P21 (0, 55)
  point P13 (-125, 0)
  point P23 (-125, 0)
  coincident P8 P21
  coincident P13 P23
  horizontal L10
  vertical L9
  dimension "d620_1" = -9.5
extrude "Estrusione1" new body sketch "Schizzo1" profile of C1 C2 L1 L2 K1 L3 L4 K2 L5 L6 L7 K3 L8 C3 C4 C5 L9 L10 along normal blind 3 named "d621_1"
work_plane "Piano di lavoro6" AlongDistance 3 named "d677_1"
sketch "Schizzo16" plane through (148.4, 0, 0) normal (-1, 0, 0) x axis (0, -1, 0)
  line L1 (82.5735, -43.5) -> (81.5735, -43.5)
  circle C1 centre (81.5735, -43.5) radius 3.5
  circle C2 centre (82.5735, -43.5) radius 5.5
  point P2 (81.5735, -43.5)
  point P4 (81.5735, -43.5)
  point P3 (82.5735, -43.5)
  point P5 (82.5735, -43.5)
  coincident P2 P4
  coincident P3 P5
  horizontal L1
  dimension "d678_1" diameter C2 = 11
  dimension "d713_1" distance P4 P5 = 1
extrude "Estrusione13" add sketch "Schizzo16" profile of C1 C2 against normal blind 6 named "d679_1"
sketch "Schizzo17" plane through (154.4, 0, 0) normal (1, 0, 0) x axis (0, 1, 0)
  line L1 (-87.2477, -40.6013) -> (-87.2477, -46.3987)
  arc A1 centre (-82.5735, -43.5) radius 5.5 clockwise from (-87.2477, -40.6013) to (-87.2477, -46.3987)
sketch "Schizzo18" plane through (0, 0, 14) normal (0, 0, 1) x axis (-1, 0, 0)
  line L1 (-135, 88.4) -> (-135, 87.65)
  line L2 (-125, 88.4) -> (-135, 88.4)
  line L3 (-125, 90) -> (-125, 88.4)
  line L4 (-160, 90) -> (-125, 90)
  line L5 (-160, 88.4) -> (-160, 90)
  curve K1 (-142.5, 81.4) -> (-160, 88.4)
  curve K2 (-135, 85.4) -> (-142.5, 81.4)
  line L6 (-135, 86.15) -> (-135, 85.4)
  line L7 (-139.6, 88.4) -> (-150.8209, 88.4)
  line L8 (-138.6, 87.4) -> (-139.6, 88.4)
  line L9 (-138.6, 87.0053) -> (-138.6, 87.4)
  line L10 (-138.6, 87.0053) -> (-139.3951, 85.3988)
  curve K3 (-142.5, 83) -> (-139.3951, 85.3988)
  curve K4 (-151.0572, 87.4594) -> (-142.5, 83)
  curve K5 (-150.8209, 88.4) -> (-151.0572, 87.4594)
  line L11 (-142.5, 72.162) -> (-142.5, 81.4)
  line L12 (-160, 72.162) -> (-142.5, 72.162)
  line L13 (-160, 88.4) -> (-160, 72.162)
  arc A1 centre (-135.4, 86.9) radius 0.85 clockwise from (-135, 86.15) to (-135, 87.65)
  point P10 (-142.5, 81.4)
  point P19 (-142.5, 81.4)
  point P9 (-160, 88.4)
  point P22 (-160, 88.4)
  coincident P10 P19
  vertical L11
  perpendicular L11 L12
  coincident P9 P22
  vertical L13
extrude "Estrusione14" cut sketch "Schizzo18" profile of K1 L11 L12 L13 against normal blind 72.864 named "d681_1"
sketch "Schizzo19" plane through (148.4, 0, 0) normal (-1, 0, 0) x axis (0, -1, 0)
  circle C1 centre (81.5735, -43.5) radius 5
  circle C2 centre (81.5735, -43.5) radius 2.45
  dimension "d683_1" diameter C1 = 10
extrude "Estrusione15" add sketch "Schizzo19" profile of C1 along normal blind 5.9 named "d684_1"
sketch "Schizzo20" plane through (148.4, 0, 0) normal (1, 0, 0) x axis (0, 1, 0)
  line L1 (-83.9651, -39.109) -> (-83.9651, -47.891)
  arc A1 centre (-81.5735, -43.5) radius 5 clockwise from (-83.9651, -39.109) to (-83.9651, -47.891)
  circle C1 centre (-81.5735, -43.5) radius 5
  concentric A1 C1
  dimension "d686_1" diameter C1 = 10
extrude "Estrusione16" cut sketch "Schizzo20" along normal blind 7.718 named "d687_1"
fillet "Raccordo1" radius 3 named "d690_1"
fillet "Raccordo2" radius 5 named "d692_1"
fillet "Raccordo3" radius 1 named "d694_1"
fillet "Raccordo4" StartRadius 3 named "d705_1" EndRadius 3 named "d706_1" MidRadius 0.2 named "d707_1" MidParams 0.5 named "d708_1"
sketch "Schizzo21" plane through (148.4, 0, 0) normal (1, 0, 0) x axis (0, 1, 0)
  curve K1 (-83.9651, -49.4206) -> (-79.9057, -47.4498)
  curve K2 (-84.564, -39.4928) -> (-83.9651, -38.4409)
  curve K3 (-79.9057, -47.4498) -> (-79.9058, -39.5505)
  curve K4 (-79.9058, -39.5505) -> (-83.9651, -37.58)
  line L1 (-83.9651, -37.58) -> (-83.9651, -38.4409)
  curve K5 (-83.9651, -48.5591) -> (-84.564, -47.5072)
  line L2 (-83.9651, -48.5591) -> (-83.9651, -49.4206)
  arc A1 centre (-81.5735, -43.5) radius 5 clockwise from (-85.8748, -40.9507) to (-84.564, -39.4928)
  arc A2 centre (-81.5735, -43.5) radius 5 clockwise from (-85.8748, -46.0493) to (-85.8748, -40.9507)
  arc A3 centre (-81.5735, -43.5) radius 5 clockwise from (-84.564, -47.5072) to (-85.8748, -46.0493)
  circle C1 centre (-81.5735, -43.5) radius 0.75
  dimension "d697_1" diameter C1 = 1.5
extrude "Estrusione17" cut sketch "Schizzo21" profile of C1 against normal blind 5.8 named "d698_1"
mirror "Specchio3" mirrorStitchTolerance 0.1 named "d712_1"
sketch "Schizzo1" plane through (0, 0, 80) normal (0, 0, -1) x axis (1, 0, 0)
  line L1 (131.5, 70.5) -> (131.5, -70.5)
  line L2 (-121.5, 80.5) -> (121.5, 80.5)
  line L3 (-131.5, -70.5) -> (-131.5, 70.5)
  line L4 (121.5, -80.5) -> (-121.5, -80.5)
  line L5 (130.8, -70.5) -> (130.8, 70.5)
  line L6 (-121.5, -79.8) -> (121.5, -79.8)
  line L7 (-130.8, 70.5) -> (-130.8, -70.5)
  line L8 (121.5, 79.8) -> (-121.5, 79.8)
  line L9 (85, 65) -> (85, 90)
  line L10 (160, 90) -> (85, 90)
  line L11 (160, 65) -> (160, 90)
  line L12 (85, 65) -> (160, 65)
  line L13 (44.15, 90) -> (50.85, 90)
  line L14 (126.65, 90) -> (133.35, 90)
  line L15 (133.35, 90) -> (126.65, 90)
  line L16 (50.85, 90) -> (44.15, 90)
  line L17 (160, 90) -> (85, 90)
  line L18 (85, 90) -> (160, 90)
  line L19 (0, 90) -> (85, 90)
  line L20 (95, 90) -> (0, 90)
  line L21 (125, 90) -> (95, 90)
  line L22 (125, 90) -> (95, 90)
  line L23 (0, 90) -> (95, 90)
  line L24 (85, 90) -> (0, 90)
  line L25 (135, 85.4) -> (95, 85.4)
  line L26 (110, 85.4) -> (95, 85.4)
  line L27 (135, 85.4) -> (129.7095, 85.4)
  curve K1 (140.5791, 82.0476) -> (142.5, 81.4)
  curve K2 (142.5, 81.4) -> (135, 85.4)
  curve K3 (142.5, 81.4) -> (135, 85.4)
  curve K4 (140.5791, 82.0476) -> (142.5, 81.4)
  line L28 (135, 85.4) -> (135, 90)
  line L29 (135, 75.4) -> (135, 85.4)
  line L30 (141, 75.4) -> (141, 81.7819)
  line L31 (141, 75.4) -> (135, 75.4)
  line L32 (110.0047, 85.4) -> (110, 85.4)
  line L33 (129.7095, 85.4) -> (110.0047, 85.4)
  arc A1 centre (121.5, -70.5) radius 10 clockwise from (131.5, -70.5) to (121.5, -80.5)
  arc A2 centre (121.5, 70.5) radius 10 clockwise from (121.5, 80.5) to (131.5, 70.5)
  arc A3 centre (-121.5, 70.5) radius 10 clockwise from (-131.5, 70.5) to (-121.5, 80.5)
  arc A4 centre (-121.5, -70.5) radius 10 clockwise from (-121.5, -80.5) to (-131.5, -70.5)
  arc A5 centre (121.5, 70.5) radius 9.3 clockwise from (121.5, 79.8) to (130.8, 70.5)
  arc A6 centre (121.5, -70.5) radius 9.3 clockwise from (130.8, -70.5) to (121.5, -79.8)
  arc A7 centre (-121.5, -70.5) radius 9.3 clockwise from (-121.5, -79.8) to (-130.8, -70.5)
  arc A8 centre (-121.5, 70.5) radius 9.3 clockwise from (-130.8, 70.5) to (-121.5, 79.8)
  point P42 (135, 90)
  point P45 (141, 81.7819)
  point P43 (135, 85.4)
  point P44 (135, 75.4)
  coincident L15 P42
  parallel L1 L29
  coincident K4 P45
  vertical L30
  perpendicular L30 L31
  dimension "d714_1" distance L11 L28 = 25
  dimension "d715_1" distance P43 P44 = 10
  dimension "d716_1" distance L29 L30 = 6
extrude "Estrusione1" new body sketch "Schizzo1" profile of K1 K2 K3 K4 L29 L30 L31 along normal blind 16 named "d717_1"
sketch "Schizzo2" plane through (0, 0, 80) normal (0, 0, 1) x axis (-1, 0, 0)
  line L1 (-135, 85.4) -> (-135, 75.4)
  curve K1 (-140.5791, 82.0476) -> (-135, 85.4)
  curve K2 (-140.5791, 82.0476) -> (-140.6931, 81.9682)
  line L2 (-140.6932, 81.9682) -> (-140.6931, 81.9682)
  curve K3 (-140.6932, 81.9682) -> (-140.9375, 81.8166)
  line L3 (-141, 75.4) -> (-141, 81.7819)
  line L4 (-135, 75.4) -> (-141, 75.4)
  line L5 (-126, 75.4) -> (-135, 75.4)
  line L6 (-126, 77.2) -> (-126, 75.4)
  curve K4 (-130, 77.2) -> (-126, 77.2)
  curve K5 (-132, 80.4) -> (-130, 77.2)
  curve K6 (-132, 85.4) -> (-132, 80.4)
  curve K7 (-135, 85.4) -> (-132, 85.4)
  curve K8 (-135, 85.4) -> (-126, 77.2)
  curve K9 (-141, 81.7819) -> (-140.5791, 82.0476)
  curve K10 (-142.3179, 80.3941) -> (-141, 81.7819)
  curve K11 (-143, 77.0196) -> (-142.3179, 80.3941)
  curve K12 (-143, 75.4) -> (-143, 77.0196)
  curve K13 (-143, 75.4) -> (-140.5791, 82.0476)
  line L7 (-141, 75.4) -> (-143, 75.4)
  closed curve K14 centre (-141.1774, 82.1553)
  point P2 (-135, 75.4)
  point P11 (-135, 75.4)
  point P8 (-141, 81.7819)
  point P17 (-141, 81.7819)
  point P10 (-141, 75.4)
  point P21 (-141, 75.4)
  point P13 (-126, 77.2)
  point P14 (-130, 77.2)
  point P15 (-132, 80.4)
  point P16 (-132, 85.4)
  point P3 (-135, 85.4)
  point P12 (-126, 75.4)
  point P20 (-143, 75.4)
  coincident P2 P11
  perpendicular L1 L5
  perpendicular L4 L6
  horizontal K7
  vertical K6
  horizontal K4
  coincident P8 P17
  coincident P10 P21
  horizontal L7
  vertical K12
  dimension "d719_1" distance P13 P14 = 4
  dimension "d720_1" distance P15 P16 = 5
  dimension "d721_1" distance P3 P16 = 3
  dimension "d722_1" distance P12 P13 = 1.8
  dimension "d742_1" distance P11 P12 = 9
  dimension "d757_1" distance P20 P21 = 2
extrude "Estrusione2" add sketch "Schizzo2" profile of L1 L3 L5 L6 K8 K13 L7 against normal blind 16 named "d725_1"
sketch "Schizzo6" plane through (0, 0, 80) normal (0, 0, 1) x axis (-1, 0, 0)
  curve K1 (-140.5791, 82.0476) -> (-135, 85.4)
  curve K2 (-140.5791, 82.0476) -> (-140.6931, 81.9682)
  line L1 (-140.6932, 81.9682) -> (-140.6931, 81.9682)
  curve K3 (-140.6932, 81.9682) -> (-140.9375, 81.8166)
  line L2 (-141, 81.6497) -> (-141, 81.7819)
  curve K4 (-143, 75.4) -> (-141, 81.6497)
  line L3 (-126, 75.4) -> (-143, 75.4)
  line L4 (-126, 77.2) -> (-126, 75.4)
  curve K5 (-135, 85.4) -> (-126, 77.2)
  line L5 (-140.5791, 82.0476) -> (-141, 81.6497)
  closed curve K6 centre (-141.1774, 82.1553)
  point P9 (-141, 81.6497)
  point P13 (-141, 81.6497)
  point P3 (-140.5791, 82.0476)
  point P14 (-140.5791, 82.0476)
  coincident P9 P13
  coincident P3 P14
extrude "Estrusione4" cut sketch "Schizzo6" profile of K2 L1 K3 K6 L2 L5 against normal blind 16 named "d754_1"
sketch "Schizzo3" plane through (0, -75.4, 0) normal (0, 1, 0) x axis (-1, 0, 0)
  line L1 (-143, 80) -> (-126, 80)
  line L2 (-126, 64) -> (-143, 64)
  line L3 (-126, 80) -> (-126, 64)
  line L4 (-139, 64) -> (-139, 80)
  line L5 (-143, 64) -> (-143, 80)
  point P6 (-139, 80)
  point P7 (-139, 64)
  point P8 (-139, 76)
  point P9 (-139, 68)
  coincident L1 P6
  coincident L2 P7
  perpendicular L2 L4
  coincident L4 P8
  coincident L4 P9
  dimension "d727_1" distance L2 P9 = 4
  dimension "d728_1" distance L1 P8 = 4
  dimension "d756_1" distance L4 L5 = 4
hole "Foratura1" HoleDepth 12 named "d729_1" HoleDiameter 3.5 named "d730_1" TipAngle 180 named "d731_1"
work_plane "Piano di lavoro1" AlongDistance -6 named "d941_1"
sketch "Schizzo7" plane through (0, -81.4, 0) normal (0, 1, 0) x axis (1, 0, 0)
  line L1 (140.75, -68) -> (140.75, -76)
  line L2 (137.25, -76) -> (137.25, -68)
  line L3 (141.25, -68) -> (141.25, -76)
  line L4 (136.75, -76) -> (136.75, -68)
  circle C1 centre (139, -76) radius 1.75
  circle C2 centre (139, -68) radius 1.75
  arc A1 centre (139, -68) radius 1.75 clockwise from (137.25, -68) to (140.75, -68)
  arc A2 centre (139, -76) radius 1.75 clockwise from (140.75, -76) to (137.25, -76)
  arc A3 centre (139, -68) radius 2.25 clockwise from (136.75, -68) to (141.25, -68)
  arc A4 centre (139, -76) radius 2.25 clockwise from (141.25, -76) to (136.75, -76)
  point P4 (140.75, -76)
  point P5 (140.75, -68)
  point P6 (137.25, -68)
  point P7 (137.25, -76)
  coincident C1 P4
  coincident C2 P5
  tangent C2 L1
  coincident C2 P6
  coincident C1 P7
  tangent C1 L2
  vertical L2
  tangent C1 L1
  concentric C1 A2
  concentric C2 A1
  dimension "d942_1" = 0.5
extrude "Estrusione5" cut sketch "Schizzo7" against normal blind 7.755 named "d943_1"
fillet "Raccordo1" radius 2 named "d733_1" 1 named "d775_1"
sketch "Schizzo4" plane through (0, -75.4, 0) normal (0, 1, 0) x axis (-1, 0, 0)
  curve K1 (-126, 78) -> (-128, 80)
  line L1 (-142, 80) -> (-128, 80)
  line L2 (-128, 64) -> (-142, 64)
  curve K2 (-128, 64) -> (-126, 66)
  line L3 (-126, 78) -> (-126, 66)
  line L4 (0, 104.9501) -> (0, 91.5)
  line L5 (0, 15.9207) -> (0, 91.5)
  line L6 (0, 80) -> (-128, 80)
  line L7 (0, 64) -> (-128, 64)
  line L8 (0, 64) -> (0, 80)
  line L9 (-143, 65) -> (-143, 79)
  curve K3 (-142, 80) -> (-143, 79)
  curve K4 (-143, 65) -> (-142, 64)
  circle C1 centre (-139, 76) radius 1.75
  circle C2 centre (-139, 68) radius 1.75
  point P8 (0, 91.5)
  point P10 (0, 91.5)
  point P2 (-128, 80)
  point P12 (-128, 80)
  point P13 (0, 80)
  point P6 (-128, 64)
  point P14 (-128, 64)
  point P15 (0, 64)
  coincident P8 P10
  parallel L4 L5
  coincident P2 P12
  coincident L5 P13
  coincident P6 P14
  coincident L5 P15
  horizontal L6
extrude "Estrusione3" new body sketch "Schizzo4" profile of K1 L1 L2 K2 L3 L6 L7 L8 C1 C2 L9 K3 K4 along normal blind 3 named "d734_1" bodies "STAFFA"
